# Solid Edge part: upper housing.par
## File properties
Author: Robert a Rhodes jr
Template: NORMENG.PAR
Last saved by: TIET
Revision: 12
Application: Solid Edge
Accuracy: 0.99
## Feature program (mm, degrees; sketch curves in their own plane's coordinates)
sketch for "unnamed Protrusion 1" plane through (0, 0, 0) normal (0, -1, 0) x-axis (1, 0, 0)
  arc centre (0, 0) radius 152.4 from (152.4, 0) to (-152.4, 0) ccw
  line (-152.4, 0) -> (152.4, 0)
extrude "unnamed Protrusion 1" add finite 203.2 symmetric
swept protrusion "SweptProtrusion_1"  Profile_5_Plane_FractionOfCurve = 0
fillet "Round_1" radius 38.1
fillet "Round_2" radius 12.7
thinwall "Thinwall_2"  Thickness = 6.35 mm
sketch for "unnamed Cutout 1" plane through (0, -101.6, 76.2) normal (0, -1, 0) x-axis (1, 0, 0)
  arc centre (0, -76.2) radius 123.825 from (-123.825, -76.2) to (123.825, -76.2) cw
extrude "unnamed Cutout 1" cut through along -normal
sketch for "unnamed Cutout 2" plane through (0, 95.25, 73.025) normal (0, -1, 0) x-axis (1, 0, 0)
  arc centre (0, -73.025) radius 38.1 from (38.1, -73.025) to (-38.1, -73.025) ccw
extrude "unnamed Cutout 2" cut through along -normal
sketch for "ExtrudedProtrusion_2" plane through (0, -101.6, 76.2) normal (0, -1, 0) x-axis (1, 0, 0)
  line (152.4, -76.2) -> (190.5, -76.2)
  line (190.5, -76.2) -> (190.5, -66.04)
  line (190.5, -66.04) -> (152.061, -66.04)
  arc centre (0, -76.2) radius 152.4 from (152.4, -76.2) to (152.061, -66.04) ccw
extrude "ExtrudedProtrusion_2" add finite 203.2 along -normal
mirror "unnamed Mirror 1" of "ExtrudedProtrusion_2" about plane through (0, 0, 0) normal (1, 0, 0)
extrude "unnamed Protrusion 2" add finite 203.2
sketch for "Hole_1" plane through (171.2507, 0, 10.16) normal (0, 0, 1) x-axis (0, 1, 0)
hole "Hole_1" diameter 10.414 through
pattern "unnamed Pattern 1" of "Hole_1"
pattern "unnamed Pattern 2"
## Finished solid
Body 1: solid body, 69 faces, 164 edges, 88 vertices.
  Faces by surface: blend 24, plane 15, cylinder 14, offset 6, spline 6, torus 4
  Edges by curve: circle 60, intersection 56, line 45, curve on surface 3
Bounding box of the edges (mm; curved faces can reach further): 492.760 x 203.200 x 255.273, from (-302.26, -101.6, 0) to (190.5, 101.6, 255.2731).
Cylindrical faces by radius (mm): R5.207 x8, R12.7 x1, R19.05 x1, R38.1 x1, R123.825 x1, R146.05 x1, R152.4 x1
Toroidal faces (ring radius, tube radius in mm): R165.1 r12.7 x2, R165.1 r19.05 x2
Planar faces by outward normal: +x 1, +y 4, +z 2, -x 2, -y 4, -z 2
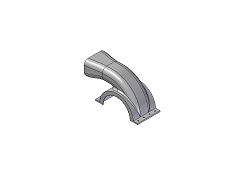
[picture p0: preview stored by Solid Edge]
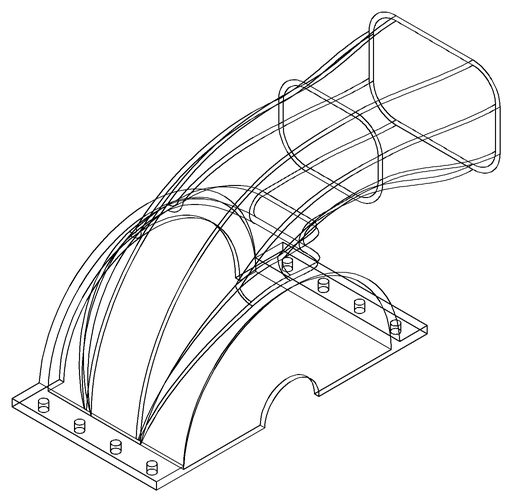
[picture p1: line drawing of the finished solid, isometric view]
